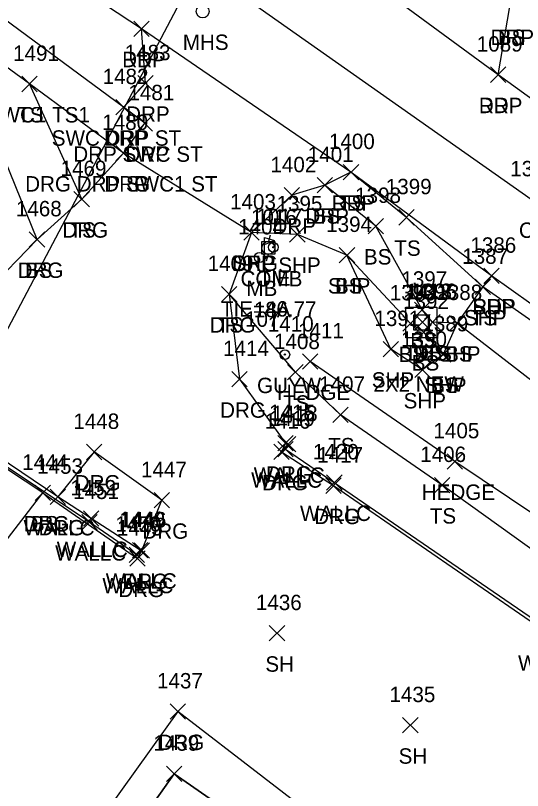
# Model space of a CAD drawing. Extents: x 1461855 to 1464118, y 556196 to 557441.
# Drawn here: x 1462417.3 to 1462483.1, y 556277.2 to 556377.9 of the extents above; entities that cross this region are included whole.
import ezdxf

# ---------------------------------------------------------------- set-up
doc = ezdxf.new("R2010")
doc.units = 0
for name, color, linetype in [('C_A', 7, 'Continuous'), ('C_C', 7, 'Continuous'), ('C_I', 7, 'Continuous'), ('CBP', 7, 'Continuous'), ('D_A', 7, 'Continuous'), ('D_C', 7, 'Continuous'), ('D_I', 7, 'Continuous'), ('D_TIC', 7, 'Continuous'), ('DCP', 7, 'Continuous'), ('DS', 7, 'Continuous'), ('L_A', 7, 'Continuous'), ('L_C', 7, 'Continuous'), ('L_I', 7, 'Continuous'), ('L_TIC', 7, 'Continuous'), ('LAHR', 7, 'Continuous'), ('LBC', 7, 'Continuous'), ('LELB', 7, 'Continuous'), ('LMB', 7, 'Continuous'), ('LSOGP', 7, 'Continuous'), ('LW', 7, 'Continuous'), ('P_A', 7, 'Continuous'), ('P_I', 7, 'Continuous'), ('P_TIC', 7, 'Continuous'), ('PET', 7, 'Continuous'), ('PRC', 7, 'Continuous'), ('PSP', 7, 'Continuous'), ('R_A', 7, 'Continuous'), ('R_I', 7, 'Continuous'), ('R_TIC', 7, 'Continuous'), ('RDG', 7, 'Continuous'), ('RDP', 7, 'Continuous'), ('RSW', 7, 'Continuous'), ('U_A', 7, 'Continuous'), ('U_C', 7, 'Continuous'), ('U_I', 7, 'Continuous'), ('UP', 7, 'Continuous'), ('UPGW', 7, 'Continuous'), ('USMH', 7, 'Continuous')]:
    doc.layers.add(name, color=color, linetype=linetype)

msp = doc.modelspace()

# ---------------------------------------------------------------- linework, layer by layer
at = {"layer": 'CBP'}
for radius in [0.625, 0.0833]:
    msp.add_circle((1462450.73, 556347.78), radius, dxfattribs=at)
at = {"layer": 'D_TIC'}
for points in [[(1462469.09, 556337.07), (1462471.09, 556339.07)], [(1462471.09, 556337.07), (1462469.09, 556339.07)]]:
    msp.add_lwpolyline(points, dxfattribs=at)
at = {"layer": 'DCP'}
msp.add_lwpolyline([(1462385.25, 556278.43), (1462450.22, 556401.67)], dxfattribs=at)
at = {"layer": 'DS'}
for p, q in [((1462467.94, 556340.01), (1462471.94, 556340.01)), ((1462467.94, 556336.01), (1462467.94, 556340.01)), ((1462471.94, 556340.01), (1462471.94, 556336.01)), ((1462468.94, 556337.01), (1462468.94, 556339.01)), ((1462468.94, 556339.01), (1462470.94, 556339.01)), ((1462470.94, 556339.01), (1462470.94, 556337.01)), ((1462469.95, 556338.01), (1462469.95, 556338.01)), ((1462469.95, 556338.01), (1462469.95, 556338.01)), ((1462470.94, 556337.01), (1462468.94, 556337.01)), ((1462471.94, 556336.01), (1462467.94, 556336.01))]:
    msp.add_line(p, q, dxfattribs=at)
at = {"layer": 'L_TIC'}
for points in [[(1462418.08, 556367.99), (1462420.08, 556369.99)], [(1462420.08, 556367.99), (1462418.08, 556369.99)], [(1462459.8, 556356.54), (1462461.8, 556358.54)], [(1462461.8, 556356.54), (1462459.8, 556358.54)], [(1462456.4, 556354.85), (1462458.4, 556356.85)], [(1462458.4, 556354.85), (1462456.4, 556356.85)], [(1462424.85, 556353.03), (1462426.85, 556355.03)], [(1462426.85, 556353.03), (1462424.85, 556355.03)], [(1462467.02, 556350.67), (1462469.02, 556352.67)], [(1462469.02, 556350.67), (1462467.02, 556352.67)], [(1462463.04, 556349.54), (1462465.04, 556351.54)], [(1462465.04, 556349.54), (1462463.04, 556351.54)], [(1462419.05, 556347.8), (1462421.05, 556349.8)], [(1462421.05, 556347.8), (1462419.05, 556349.8)], [(1462459.28, 556345.77), (1462461.28, 556347.77)], [(1462461.28, 556345.77), (1462459.28, 556347.77)], [(1462476.93, 556341.63), (1462478.93, 556343.63)], [(1462478.93, 556341.63), (1462476.93, 556343.63)], [(1462443.98, 556340.7), (1462445.98, 556342.7)], [(1462445.98, 556340.7), (1462443.98, 556342.7)], [(1462469.04, 556338.66), (1462471.04, 556340.66)], [(1462471.04, 556338.66), (1462469.04, 556340.66)], [(1462467.54, 556336.88), (1462469.54, 556338.88)], [(1462469.54, 556336.88), (1462467.54, 556338.88)], [(1462470.37, 556337.06), (1462472.37, 556339.06)], [(1462472.37, 556337.06), (1462470.37, 556339.06)], [(1462473.58, 556336.93), (1462475.58, 556338.93)], [(1462475.58, 556336.93), (1462473.58, 556338.93)], [(1462469.25, 556335.77), (1462471.25, 556337.77)], [(1462471.25, 556335.77), (1462469.25, 556337.77)], [(1462471.77, 556332.86), (1462473.77, 556334.86)], [(1462473.77, 556332.86), (1462471.77, 556334.86)], [(1462454.49, 556331.95), (1462456.49, 556333.95)], [(1462456.49, 556331.95), (1462454.49, 556333.95)], [(1462452.58, 556330.55), (1462454.58, 556332.55)], [(1462454.58, 556330.55), (1462452.58, 556332.55)], [(1462458.44, 556325.01), (1462460.44, 556327.01)], [(1462460.44, 556325.01), (1462458.44, 556327.01)], [(1462451.64, 556321.19), (1462453.64, 556323.19)], [(1462453.64, 556321.19), (1462451.64, 556323.19)], [(1462451.31, 556320.55), (1462453.31, 556322.55)], [(1462453.31, 556320.55), (1462451.31, 556322.55)], [(1462473.29, 556318.97), (1462475.29, 556320.97)], [(1462475.29, 556318.97), (1462473.29, 556320.97)], [(1462457.64, 556316.23), (1462459.64, 556318.23)], [(1462459.64, 556316.23), (1462457.64, 556318.23)], [(1462471.62, 556315.89), (1462473.62, 556317.89)], [(1462473.62, 556315.89), (1462471.62, 556317.89)], [(1462419.82, 556314.87), (1462421.82, 556316.87)], [(1462421.82, 556314.87), (1462419.82, 556316.87)], [(1462421.77, 556314.36), (1462423.77, 556316.36)], [(1462423.77, 556314.36), (1462421.77, 556316.36)], [(1462425.87, 556311.08), (1462427.87, 556313.08)], [(1462427.87, 556311.08), (1462425.87, 556313.08)], [(1462426.08, 556311.55), (1462428.08, 556313.55)], [(1462428.08, 556311.55), (1462426.08, 556313.55)], [(1462432.43, 556307.44), (1462434.43, 556309.44)], [(1462434.43, 556307.44), (1462432.43, 556309.44)], [(1462432.43, 556307.44), (1462434.43, 556309.44)], [(1462434.43, 556307.44), (1462432.43, 556309.44)], [(1462432, 556306.84), (1462434, 556308.84)], [(1462434, 556306.84), (1462432, 556308.84)], [(1462450.2, 556296.65), (1462452.2, 556298.65)], [(1462452.2, 556296.65), (1462450.2, 556298.65)], [(1462467.5, 556284.7), (1462469.5, 556286.7)], [(1462469.5, 556284.7), (1462467.5, 556286.7)], [(1462436.85, 556278.39), (1462438.85, 556280.39)], [(1462438.85, 556278.39), (1462436.85, 556280.39)]]:
    msp.add_lwpolyline(points, dxfattribs=at)
at = {"layer": 'LAHR'}
msp.add_lwpolyline([(1462499.25, 556303.19), (1462474.29, 556319.97), (1462455.49, 556332.95)], dxfattribs=at)
at = {"layer": 'LBC'}
msp.add_lwpolyline([(1462469.3, 556257.51), (1462437.85, 556279.39), (1462423.63, 556259.27)], dxfattribs=at)
at = {"layer": 'LELB'}
for points in [[(1462420.05, 556348.8), (1462413.65, 556364.51), (1462410.64, 556367.91), (1462395.05, 556380.65), (1462391.53, 556382.1), (1462377.14, 556389.53), (1462361.29, 556393.39)], [(1462425.85, 556354.03), (1462419.08, 556368.99)], [(1462599.06, 556233.38), (1462596.16, 556246.32), (1462592.2, 556257.91), (1462576.23, 556267.47), (1462557.62, 556278.83), (1462540.3, 556283.77), (1462528.89, 556296.86), (1462529.08, 556306.21), (1462517.11, 556315.38), (1462502.07, 556325.71), (1462477.93, 556342.63), (1462468.02, 556351.67), (1462460.8, 556357.54)], [(1462566.05, 556253.25), (1462551.07, 556261.22), (1462526.69, 556275.99), (1462519.12, 556289.53), (1462518.52, 556300.62), (1462520.17, 556306.41), (1462512.78, 556309.97), (1462497.67, 556320.06), (1462474.58, 556337.93), (1462471.37, 556338.06), (1462470.04, 556339.66), (1462464.04, 556350.54), (1462457.4, 556355.85)], [(1462420.82, 556315.87), (1462399.72, 556329.77), (1462399.11, 556332.97), (1462393.77, 556336.69), (1462391.87, 556346.72)], [(1462472.77, 556333.86), (1462470.25, 556336.77), (1462468.54, 556337.88), (1462460.28, 556346.77)], [(1462503.75, 556294.55), (1462472.62, 556316.89), (1462459.44, 556326.01), (1462453.58, 556331.55), (1462444.98, 556341.7)]]:
    msp.add_lwpolyline(points, dxfattribs=at)
at = {"layer": 'LMB'}
for p, q in [((1462449.58, 556349.05), (1462450.87, 556348.67)), ((1462449.58, 556346.46), (1462449.58, 556349.05)), ((1462449.58, 556348.15), (1462450.87, 556348.66)), ((1462448.93, 556346.45), (1462448.93, 556346.45))]:
    msp.add_line(p, q, dxfattribs=at)
msp.add_circle((1462448.93, 556346.45), 0.656, dxfattribs=at)
at = {"layer": 'LSOGP'}
msp.add_lwpolyline([(1462417.02, 556268.29), (1462422.03, 556264.7), (1462423.63, 556259.27), (1462437.85, 556279.39), (1462469.3, 556257.51), (1462473.36, 556252.36), (1462475.99, 556251.86), (1462480.92, 556253.43), (1462498.64, 556238.67), (1462531.2, 556230.03), (1462548.24, 556252.72)], dxfattribs=at)
at = {"layer": 'LW'}
for points in [[(1462433.43, 556308.44), (1462433, 556307.84), (1462426.87, 556312.08), (1462400.05, 556329.95), (1462399.44, 556332.88), (1462393.96, 556336.86), (1462392.2, 556346.64)], [(1462433.43, 556308.44), (1462427.08, 556312.55), (1462422.77, 556315.36), (1462400.71, 556330.27), (1462399.98, 556333.44), (1462394.64, 556337.24)], [(1462452.64, 556322.19), (1462452.31, 556321.55), (1462458.64, 556317.23), (1462486.94, 556297.79), (1462493.1, 556293.38), (1462493.53, 556293.87)]]:
    msp.add_lwpolyline(points, dxfattribs=at)
at = {"layer": 'P_TIC'}
for points in [[(1462432.62, 556375.17), (1462434.62, 556377.17)], [(1462434.62, 556375.17), (1462432.62, 556377.17)], [(1462478.91, 556369.2), (1462480.91, 556371.2)], [(1462480.91, 556369.2), (1462478.91, 556371.2)], [(1462459.8, 556356.54), (1462461.8, 556358.54)], [(1462461.8, 556356.54), (1462459.8, 556358.54)], [(1462446.88, 556348.7), (1462448.88, 556350.7)], [(1462448.88, 556348.7), (1462446.88, 556350.7)], [(1462452.84, 556348.46), (1462454.84, 556350.46)], [(1462454.84, 556348.46), (1462452.84, 556350.46)], [(1462459.28, 556345.77), (1462461.28, 556347.77)], [(1462461.28, 556345.77), (1462459.28, 556347.77)], [(1462478.05, 556343.07), (1462480.05, 556345.07)], [(1462480.05, 556343.07), (1462478.05, 556345.07)], [(1462478.05, 556343.07), (1462480.05, 556345.07)], [(1462480.05, 556343.07), (1462478.05, 556345.07)], [(1462476.93, 556341.63), (1462478.93, 556343.63)], [(1462478.93, 556341.63), (1462476.93, 556343.63)], [(1462473.58, 556336.93), (1462475.58, 556338.93)], [(1462475.58, 556336.93), (1462473.58, 556338.93)], [(1462464.96, 556333.55), (1462466.96, 556335.55)], [(1462466.96, 556333.55), (1462464.96, 556335.55)], [(1462471.77, 556332.86), (1462473.77, 556334.86)], [(1462473.77, 556332.86), (1462471.77, 556334.86)], [(1462469.09, 556330.85), (1462471.09, 556332.85)], [(1462471.09, 556330.85), (1462469.09, 556332.85)]]:
    msp.add_lwpolyline(points, dxfattribs=at)
at = {"layer": 'PET'}
for points in [[(1462655.57, 556260.33), (1462622.29, 556278.34), (1462596.05, 556293.11), (1462579.48, 556302.48), (1462555.03, 556317.39), (1462538.38, 556329.05), (1462522.59, 556339.78), (1462499.49, 556355.96), (1462479.91, 556370.2), (1462462.39, 556383.08), (1462450, 556394.49), (1462423.07, 556412.09), (1462414.08, 556417.65), (1462394.93, 556425.92), (1462382.48, 556434.45), (1462359.05, 556435.71), (1462354.93, 556436.4), (1462348.34, 556437.43), (1462333.33, 556438.52), (1462332.9, 556427.26)], [(1462646.26, 556240.88), (1462638.39, 556245.28), (1462613.44, 556258.88), (1462582.21, 556275.54), (1462550.05, 556294.22), (1462512.2, 556320.44), (1462479.05, 556344.07), (1462460.8, 556357.54), (1462433.62, 556376.17), (1462410.33, 556391.48), (1462383.13, 556406.1), (1462371.43, 556410.47), (1462364.34, 556412.93), (1462357.61, 556414.67), (1462347.76, 556416.01), (1462332.39, 556416.61), (1462332.9, 556427.26)]]:
    msp.add_lwpolyline(points, dxfattribs=at)
at = {"layer": 'PRC'}
msp.add_lwpolyline([(1462651.54, 556250.53), (1462619.54, 556268.24), (1462587.25, 556285.55), (1462556.86, 556302.79), (1462518.1, 556329.05), (1462484.17, 556354), (1462438.09, 556386.5), (1462416.23, 556401.26), (1462387.08, 556415.75), (1462366.36, 556422.8), (1462356.92, 556424.51), (1462339.71, 556426.54), (1462332.9, 556427.26)], dxfattribs=at)
at = {"layer": 'PSP'}
msp.add_lwpolyline([(1462479.05, 556344.07), (1462477.93, 556342.63), (1462474.58, 556337.93), (1462472.77, 556333.86), (1462470.09, 556331.85), (1462465.96, 556334.55), (1462460.28, 556346.77), (1462453.84, 556349.46), (1462447.88, 556349.7)], dxfattribs=at)
at = {"layer": 'R_TIC'}
for points in [[(1462432.62, 556375.17), (1462434.62, 556377.17)], [(1462434.62, 556375.17), (1462432.62, 556377.17)], [(1462478.91, 556369.2), (1462480.91, 556371.2)], [(1462480.91, 556369.2), (1462478.91, 556371.2)], [(1462418.08, 556367.99), (1462420.08, 556369.99)], [(1462420.08, 556367.99), (1462418.08, 556369.99)], [(1462433.13, 556368.08), (1462435.13, 556370.08)], [(1462435.13, 556368.08), (1462433.13, 556370.08)], [(1462430.26, 556364.97), (1462432.26, 556366.97)], [(1462432.26, 556364.97), (1462430.26, 556366.97)], [(1462430.26, 556364.97), (1462432.26, 556366.97)], [(1462432.26, 556364.97), (1462430.26, 556366.97)], [(1462433.04, 556362.88), (1462435.04, 556364.88)], [(1462435.04, 556362.88), (1462433.04, 556364.88)], [(1462433.04, 556362.88), (1462435.04, 556364.88)], [(1462435.04, 556362.88), (1462433.04, 556364.88)], [(1462430.29, 556359.02), (1462432.29, 556361.02)], [(1462432.29, 556359.02), (1462430.29, 556361.02)], [(1462430.29, 556359.02), (1462432.29, 556361.02)], [(1462432.29, 556359.02), (1462430.29, 556361.02)], [(1462430.29, 556359.02), (1462432.29, 556361.02)], [(1462432.29, 556359.02), (1462430.29, 556361.02)], [(1462459.8, 556356.54), (1462461.8, 556358.54)], [(1462461.8, 556356.54), (1462459.8, 556358.54)], [(1462456.4, 556354.85), (1462458.4, 556356.85)], [(1462458.4, 556354.85), (1462456.4, 556356.85)], [(1462452.12, 556353.53), (1462454.12, 556355.53)], [(1462454.12, 556353.53), (1462452.12, 556355.53)], [(1462424.85, 556353.03), (1462426.85, 556355.03)], [(1462426.85, 556353.03), (1462424.85, 556355.03)], [(1462446.88, 556348.7), (1462448.88, 556350.7)], [(1462448.88, 556348.7), (1462446.88, 556350.7)], [(1462446.88, 556348.7), (1462448.88, 556350.7)], [(1462448.88, 556348.7), (1462446.88, 556350.7)], [(1462419.05, 556347.8), (1462421.05, 556349.8)], [(1462421.05, 556347.8), (1462419.05, 556349.8)], [(1462443.98, 556340.7), (1462445.98, 556342.7)], [(1462445.98, 556340.7), (1462443.98, 556342.7)], [(1462445.33, 556329.64), (1462447.33, 556331.64)], [(1462447.33, 556329.64), (1462445.33, 556331.64)], [(1462451.29, 556321.34), (1462453.29, 556323.34)], [(1462453.29, 556321.34), (1462451.29, 556323.34)], [(1462426.47, 556320.19), (1462428.47, 556322.19)], [(1462428.47, 556320.19), (1462426.47, 556322.19)], [(1462450.77, 556320.22), (1462452.77, 556322.22)], [(1462452.77, 556320.22), (1462450.77, 556322.22)], [(1462457.54, 556315.82), (1462459.54, 556317.82)], [(1462459.54, 556315.82), (1462457.54, 556317.82)], [(1462419.82, 556314.87), (1462421.82, 556316.87)], [(1462421.82, 556314.87), (1462419.82, 556316.87)], [(1462421.77, 556314.36), (1462423.77, 556316.36)], [(1462423.77, 556314.36), (1462421.77, 556316.36)], [(1462435.24, 556313.92), (1462437.24, 556315.92)], [(1462437.24, 556313.92), (1462435.24, 556315.92)], [(1462432.65, 556307.39), (1462434.65, 556309.39)], [(1462434.65, 556307.39), (1462432.65, 556309.39)], [(1462432.11, 556306.34), (1462434.11, 556308.34)], [(1462434.11, 556306.34), (1462432.11, 556308.34)], [(1462437.32, 556286.48), (1462439.32, 556288.48)], [(1462439.32, 556286.48), (1462437.32, 556288.48)]]:
    msp.add_lwpolyline(points, dxfattribs=at)
at = {"layer": 'RDG'}
for points in [[(1462400.71, 556330.27), (1462413.48, 556342.04), (1462420.05, 556348.8), (1462425.85, 556354.03), (1462431.29, 556360.02)], [(1462447.88, 556349.7), (1462444.98, 556341.7), (1462446.33, 556330.64), (1462452.29, 556322.34), (1462451.77, 556321.22), (1462458.54, 556316.82), (1462486.7, 556297.43), (1462493.25, 556293.06), (1462488.21, 556282.83), (1462474.76, 556259.52)], [(1462471.7, 556261.76), (1462438.32, 556287.48), (1462422.03, 556264.7), (1462402, 556279.05), (1462397.58, 556285.55), (1462409, 556300.55), (1462420.82, 556315.87), (1462433.11, 556307.34), (1462433.65, 556308.39), (1462436.24, 556314.92), (1462427.47, 556321.19), (1462422.77, 556315.36)]]:
    msp.add_lwpolyline(points, dxfattribs=at)
at = {"layer": 'RDP'}
for points in [[(1462479.91, 556370.2), (1462481.42, 556379.06), (1462486.8, 556388.15), (1462496.79, 556398.3), (1462515.3, 556415.44), (1462519.07, 556419.29), (1462512.47, 556425.79)], [(1462431.26, 556365.97), (1462434.13, 556369.08), (1462433.62, 556376.17)], [(1462460.8, 556357.54), (1462457.4, 556355.85), (1462453.12, 556354.53), (1462447.88, 556349.7), (1462431.29, 556360.02), (1462434.04, 556363.88)]]:
    msp.add_lwpolyline(points, dxfattribs=at)
at = {"layer": 'RSW'}
for points in [[(1462431.29, 556360.02), (1462419.08, 556368.99), (1462398.06, 556384.44), (1462394.86, 556386.88), (1462377.7, 556396.26), (1462367.93, 556400), (1462360.45, 556401.77), (1462356.52, 556402.46), (1462338.78, 556403.56), (1462339.2, 556408.46)], [(1462434.04, 556363.88), (1462431.26, 556365.97), (1462399.1, 556389.81), (1462379.57, 556400.67), (1462369.22, 556404.8), (1462358.88, 556407.08), (1462339.2, 556408.46)]]:
    msp.add_lwpolyline(points, dxfattribs=at)
at = {"layer": 'UP'}
for p, q in [((1462450.33, 556349.37), (1462450.08, 556348.54)), ((1462449.25, 556346.87), (1462449.25, 556348.54)), ((1462449.25, 556348.54), (1462450.92, 556348.54)), ((1462450.92, 556348.54), (1462450.92, 556346.87)), ((1462450.08, 556347.7), (1462450.08, 556347.7)), ((1462450.92, 556346.87), (1462449.25, 556346.87)), ((1462449.83, 556346.04), (1462450.08, 556346.87))]:
    msp.add_line(p, q, dxfattribs=at)
msp.add_circle((1462450.08, 556347.7), 0.833, dxfattribs=at)
at = {"layer": 'UPGW'}
for radius in [0.625, 0.0833]:
    msp.add_circle((1462452.22, 556333.84), radius, dxfattribs=at)
at = {"layer": 'USMH'}
msp.add_circle((1462441.56, 556378.41), 0.833, dxfattribs=at)

# ---------------------------------------------------------------- texts
at = {"layer": 'C_A'}
msp.add_text('TIE', height=2, dxfattribs=at).set_placement((1462448.81, 556342.78))
at = {"layer": 'C_C'}
msp.add_text('TIE=46.77', height=2, dxfattribs=at).set_placement((1462443.91, 556338.78))
at = {"layer": 'C_I'}
msp.add_text('1017', height=2, dxfattribs=at).set_placement((1462448.53, 556350.78))
at = {"layer": 'D_A'}
for s, p in [('DIB', (1462468.2, 556333.07)), ('DI', (1462469, 556333.01))]:
    msp.add_text(s, height=2, dxfattribs=at).set_placement(p)
at = {"layer": 'D_C'}
msp.add_text('2X2 NEW', height=2, dxfattribs=at).set_placement((1462463.71, 556329.01))
at = {"layer": 'D_I'}
for s, p in [('1412', (1462467.82, 556341.01)), ('1413', (1462467.97, 556341.07))]:
    msp.add_text(s, height=2, dxfattribs=at).set_placement(p)
at = {"layer": 'L_A'}
for s, p in [('BS', (1462479.86, 556374.06)), ('TS', (1462417.49, 556363.99)), ('TS', (1462459.21, 556352.54)), ('BS', (1462455.84, 556350.85)), ('TS', (1462424.26, 556349.03)), ('TS', (1462466.43, 556346.67)), ('BS', (1462462.48, 556345.54)), ('BS', (1462418.49, 556343.8)), ('MB', (1462447.23, 556341.45)), ('BS', (1462458.72, 556341.77)), ('TS', (1462476.34, 556337.63)), ('TS', (1462443.39, 556336.7)), ('BS', (1462468.48, 556334.66)), ('BS', (1462466.98, 556332.88)), ('BS', (1462469.81, 556333.06)), ('BS', (1462473.02, 556332.93)), ('BS', (1462468.69, 556331.77)), ('BS', (1462471.21, 556328.86)), ('HEDGE', (1462451.19, 556327.95)), ('TS', (1462451.99, 556326.55)), ('TS', (1462457.85, 556321.01)), ('WALLC', (1462448.18, 556317.19)), ('WALLC', (1462447.84, 556316.55)), ('HEDGE', (1462469.99, 556314.97)), ('WALLC', (1462454.18, 556312.23)), ('TS', (1462471.03, 556311.89)), ('WALLC', (1462418.3, 556310.36)), ('BS', (1462419.26, 556310.87)), ('WALLC', (1462422.4, 556307.08)), ('WALLC', (1462422.61, 556307.55)), ('WALLC', (1462428.97, 556303.44)), ('WALLC', (1462428.97, 556303.44)), ('WALLC', (1462428.53, 556302.84)), ('SH', (1462449.69, 556292.65)), ('WALLC', (1462482.48, 556292.79)), ('SH', (1462466.98, 556280.7))]:
    msp.add_text(s, height=2, dxfattribs=at).set_placement(p)
at = {"layer": 'L_C'}
msp.add_text('107', height=2, dxfattribs=at).set_placement((1462447.05, 556337.45))
at = {"layer": 'L_I'}
for s, p in [('1491', (1462416.95, 556371.99)), ('1400', (1462457.94, 556360.54)), ('1401', (1462455.2, 556358.85)), ('1469', (1462423.11, 556357.03)), ('1399', (1462465.32, 556354.67)), ('1398', (1462461.34, 556353.54)), ('1468', (1462417.31, 556351.8)), ('1404', (1462446.16, 556349.45)), ('1394', (1462457.58, 556349.77)), ('1387', (1462475.24, 556345.63)), ('1409', (1462442.2, 556344.7)), ('1397', (1462467.34, 556342.66)), ('1393', (1462465.84, 556340.88)), ('1396', (1462468.62, 556341.06)), ('1388', (1462471.88, 556340.93)), ('1392', (1462467.56, 556339.77)), ('1389', (1462470.07, 556336.86)), ('1411', (1462453.93, 556335.95)), ('1408', (1462450.81, 556334.55)), ('1407', (1462456.67, 556329.01)), ('1418', (1462450.52, 556325.19)), ('1419', (1462450.17, 556324.55)), ('1405', (1462471.51, 556322.97)), ('1420', (1462455.86, 556320.23)), ('1406', (1462469.79, 556319.89)), ('1444', (1462418.13, 556318.87)), ('1453', (1462420.07, 556318.36)), ('1452', (1462424.38, 556315.55)), ('1451', (1462424.74, 556315.08)), ('1449', (1462430.73, 556311.44)), ('1449', (1462430.73, 556311.44)), ('1450', (1462430.22, 556310.84)), ('1436', (1462448.46, 556300.65)), ('1435', (1462465.8, 556288.7)), ('1439', (1462435.15, 556282.39))]:
    msp.add_text(s, height=2, dxfattribs=at).set_placement(p)
at = {"layer": 'P_A'}
for s, p in [('RDP', (1462431.11, 556371.17)), ('RDP', (1462477.4, 556365.2)), ('RDP', (1462458.29, 556352.54)), ('CR', (1462482.6, 556349)), ('SHP', (1462445.42, 556344.7)), ('SHP', (1462451.37, 556344.46)), ('SHP', (1462457.81, 556341.77)), ('SHP', (1462476.58, 556339.07)), ('RDP', (1462476.54, 556339.07)), ('SHP', (1462475.47, 556337.63)), ('SHP', (1462472.11, 556332.93)), ('SHP', (1462463.5, 556329.55)), ('SHP', (1462470.3, 556328.86)), ('SHP', (1462467.63, 556326.85))]:
    msp.add_text(s, height=2, dxfattribs=at).set_placement(p)
at = {"layer": 'P_I'}
for s, p in [('1089', (1462477.13, 556373.2)), ('1400', (1462457.94, 556360.54)), ('1385', (1462481.47, 556357)), ('1403', (1462445.11, 556352.7)), ('1395', (1462451.14, 556352.46)), ('1394', (1462457.58, 556349.77)), ('1386', (1462476.3, 556347.07)), ('1386', (1462476.3, 556347.07)), ('1387', (1462475.24, 556345.63)), ('1388', (1462471.88, 556340.93)), ('1391', (1462463.84, 556337.55)), ('1389', (1462470.07, 556336.86)), ('1390', (1462467.31, 556334.85))]:
    msp.add_text(s, height=2, dxfattribs=at).set_placement(p)
at = {"layer": 'R_A'}
for s, p in [('DRP', (1462478.91, 556374.06)), ('DRP', (1462431.11, 556371.17)), ('DRP', (1462477.4, 556365.2)), ('SWC1 TS1', (1462413.54, 556363.99)), ('DRP', (1462431.62, 556364.08)), ('SWC DRP ST', (1462421.97, 556360.97)), ('DRP', (1462428.75, 556360.97)), ('DRP SWC ST', (1462424.76, 556358.88)), ('DRP', (1462431.53, 556358.88)), ('DRG DRP SWC1 ST', (1462418.52, 556355.02)), ('DRG', (1462428.78, 556355.02)), ('DRP', (1462428.78, 556355.02)), ('DRP', (1462458.29, 556352.54)), ('DRP', (1462454.89, 556350.85)), ('DRP', (1462450.61, 556349.53)), ('DRG', (1462423.34, 556349.03)), ('DRG', (1462445.37, 556344.7)), ('DRP', (1462445.37, 556344.7)), ('DRG', (1462417.54, 556343.8)), ('DRG', (1462442.47, 556336.7)), ('DRG', (1462443.81, 556325.64)), ('DRG', (1462449.78, 556317.34)), ('DRG', (1462424.95, 556316.19)), ('DRG', (1462449.26, 556316.22)), ('DRG', (1462456.03, 556311.82)), ('DRG', (1462418.31, 556310.87)), ('DRG', (1462420.25, 556310.36)), ('DRG', (1462433.73, 556309.92)), ('DRG', (1462431.13, 556303.39)), ('DRG', (1462430.6, 556302.34)), ('DRG', (1462435.81, 556282.48))]:
    msp.add_text(s, height=2, dxfattribs=at).set_placement(p)
at = {"layer": 'R_I'}
for s, p in [('1089', (1462477.13, 556373.2)), ('1491', (1462416.95, 556371.99)), ('1483', (1462431.43, 556372.08)), ('1482', (1462428.57, 556368.97)), ('1482', (1462428.57, 556368.97)), ('1481', (1462431.92, 556366.88)), ('1481', (1462431.92, 556366.88)), ('1480', (1462428.52, 556363.02)), ('1480', (1462428.52, 556363.02)), ('1480', (1462428.52, 556363.02)), ('1400', (1462457.94, 556360.54)), ('1401', (1462455.2, 556358.85)), ('1402', (1462450.35, 556357.53)), ('1469', (1462423.11, 556357.03)), ('1403', (1462445.11, 556352.7)), ('1403', (1462445.11, 556352.7)), ('1468', (1462417.31, 556351.8)), ('1409', (1462442.2, 556344.7)), ('1414', (1462444.2, 556333.64)), ('1415', (1462450.17, 556325.34)), ('1448', (1462424.77, 556324.19)), ('1416', (1462449.59, 556324.22)), ('1417', (1462456.42, 556319.82)), ('1444', (1462418.13, 556318.87)), ('1453', (1462420.07, 556318.36)), ('1447', (1462433.55, 556317.92)), ('1446', (1462430.9, 556311.39)), ('1445', (1462430.42, 556310.34)), ('1437', (1462435.63, 556290.48))]:
    msp.add_text(s, height=2, dxfattribs=at).set_placement(p)
at = {"layer": 'U_A'}
for s, p in [('MHS', (1462438.97, 556373.41)), ('COMB', (1462446.47, 556342.7)), ('GUYW', (1462448.61, 556328.84))]:
    msp.add_text(s, height=2, dxfattribs=at).set_placement(p)
at = {"layer": 'U_C'}
msp.add_text('18A', height=2, dxfattribs=at).set_placement((1462448.2, 556338.7))
at = {"layer": 'U_I'}
for s, p in [('1016', (1462447.82, 556350.7)), ('1410', (1462450.01, 556336.84))]:
    msp.add_text(s, height=2, dxfattribs=at).set_placement(p)

doc.saveas('drawing.dxf')
